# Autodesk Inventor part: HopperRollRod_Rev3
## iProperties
Created: 2009-01
Part Number: HopperRollRod_Rev3
Document SubType Name: Modeling
Designer: claivier
Norme de conversion: STEP AP214IS
Nom du fichier: HopperRollRod_Rev3.STEP
Préprocesseur: SolidWorks 2008
Postprocesseur: Build: 344a, Release: 11 SP2 - Date: Fri 08/18/2006
Unités envoyées: INCHES
Incertitude: 1e-05
Author: claivier
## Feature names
1. Base1
